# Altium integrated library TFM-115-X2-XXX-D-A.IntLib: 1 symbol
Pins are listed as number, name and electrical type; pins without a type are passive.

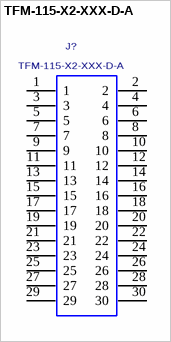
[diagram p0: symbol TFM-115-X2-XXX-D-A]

## TFM-115-X2-XXX-D-A
designator J?
0.050" TERMINAL STRIP, SURFACE MOUNT ASSEMBLY.; MANUFACTURER: SAMTEC
footprint TFM-115-X2-XXX-D-A
pins: 1, 2, 3, 4, 5, 6, 7, 8, 9, 10, 11, 12, 13, 14, 15, 16, 17, 18, 19, 20, 21, 22, 23, 24, 25, 26, 27, 28, 29, 30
